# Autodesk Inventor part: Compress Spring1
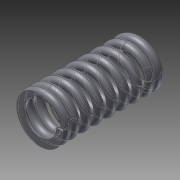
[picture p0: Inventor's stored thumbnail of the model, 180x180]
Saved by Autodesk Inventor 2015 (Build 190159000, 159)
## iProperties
Created: 2014-07
Part Number: Compress Spring1
Material: Steel, Carbon
Document SubType Name: Modeling
Designer: User
Density: 2.18 g/cm^3
Appearance: Semi-Polished
CustomPartVersion: 1
Author: User
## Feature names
1. Main Coil Feature(R)
2. Start Transition Coil 1(Right)
3. Coil  Start Transition 2(R)
4. Coil  Start Transition 3(R)
5. Coil  Start Transition 4(R)
6. Start Ends Coil(Right)
7. Start Cut Feature(Right) [Extrusion]
8. End Transition Coil 1(Right)
9. End Transition Coil 2(Right)
10. End Transition Coil 3(Right)
11. End Transition Coil 4(Right)
12. End Coil(Right)
13. End Cut Feature(Right) [Extrusion]
14. Plain Ends Cut Feature 1(Right) [Extrusion]
15. Plain Ends Cut  2(R) [Extrusion]
16. Main Coil Feature(L)
17. Start Transition Coil 1(Left)
18. Start Transition Coil 2(Left)
19. Start Transition Coil 3(Left)
20. Start Transition Coil 4(Left)
21. Start Ends Coil(Left)
22. Start Cut Feature(Left) [Extrusion]
23. End Transition Coil 1(Left)
24. End Transition Coil 2(Left)
25. End Transition Coil 3(Left)
26. End Transition Coil 4(Left)
27. End Coil(Left)
28. End Cut Feature(Left) [Extrusion]
29. Cut Plain Ends Cut 1(L) [Extrusion]
30. Cut Plain Ends Cut 2(L) [Extrusion]
## Parameters: d0 = 0.3125 mm, da_d = 1.25 mm, da_D2 = 5 mm, da_ti = 2.00104 mm, da_nz1 = 15 mm, spiral_Angle = 1.01562 mm, d2 = 2.00104 mm, d4 = 52.5 mm, d5 = 0, d6 = 90 deg, d7 = 90 deg, d8 = 0, d9 = 0, d12 = 2.39875 mm, d13 = -3.09578 mm, d14 = 1.25 mm, d15 = 0, d16 = 1.81328 mm, d18 = 2.5 mm, d19 = 0, d20 = 90 deg, d21 = 90 deg, d22 = 0, d23 = 0, d24 = 1.62552 mm, d26 = 2.5 mm, d27 = 0, d28 = 90 deg, d29 = 90 deg, d30 = 0, d31 = 0, d32 = 1.43776 mm, d34 = 2.5 mm, d35 = 0, d36 = 90 deg, d37 = 90 deg, d38 = 0, d39 = 0, d40 = 1.25 mm, d42 = 2.5 mm, d43 = 0, d44 = 90 deg, d45 = 90 deg, d46 = 0, d47 = 0, d48 = 1.81328 mm, d50 = 1.875 mm, d51 = 0, d52 = 90 deg, d53 = 90 deg, d54 = 0, d55 = 0, d56 = 1.62552 mm, d58 = 1.875 mm, d59 = 0, d60 = 90 deg, d61 = 90 deg, d62 = 0, d63 = 0, d64 = 1.43776 mm, d66 = 1.875 mm, d67 = 0, d68 = 90 deg, d69 = 90 deg, d70 = 0, d71 = 0, d72 = 1.25 mm, d74 = 1.875 mm, d75 = 0, d76 = 90 deg, d77 = 90 deg, d78 = 0, d79 = 0, End_Pitch = 1.25647 mm, d82 = 15 mm, d83 = 0, d84 = 90 deg, d85 = 90 deg, d86 = 0, d87 = 0, d88 = 1.25647 mm, d91 = 0, d92 = 90 deg, d93 = 90 deg, d94 = 0, d95 = 0, d96 = 7.5 mm, d97 = 1.25647 mm, d98 = 0, d99 = 7.5 mm, d100 = 1.25647 mm, d101 = 0, d102 = 0, d103 = 0, d104 = 0, d105 = 0, d106 = 0, d108 = 0, d112 = 0, d113 = 0, d114 = 0, const_zero = 0, Not_rightdir = 0, d121 = 0.32058 mm, d131 = 0, d132 = 0, d133 = 0, d134 = 0, d135 = 0.3125 mm, d137 = 2.00104 mm, d139 = 52.5 mm, d140 = 0, d141 = 90 deg, d142 = 90 deg, d143 = 0, d144 = 0, d145 = 2.39875 mm, d146 = -3.09578 mm, d147 = 0.32058 mm, d148 = 0.00646 mm, d149 = 1.25 mm, d150 = 0, d151 = 0, d152 = 1.81328 mm, d154 = 2.5 mm, d155 = 0, d156 = 90 deg, d157 = 90 deg, d158 = 0, d159 = 0, d160 = 1.62552 mm, d162 = 2.5 mm, d163 = 0, d164 = 90 deg, d165 = 90 deg, d166 = 0, d167 = 0, d168 = 1.43776 mm, d170 = 2.5 mm, d171 = 0, d172 = 90 deg, d173 = 90 deg, d174 = 0, d175 = 0, d176 = 1.25 mm, d178 = 2.5 mm, d179 = 0, d180 = 90 deg, d181 = 90 deg, d182 = 0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
